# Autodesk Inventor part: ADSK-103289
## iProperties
Shininess: 0.0
Created: 2000-04
Part Number: ADSK-103289
Document SubType Name: Modeling
Stock Number: ADSK-103289
Density: 1 g/cm^3
Density: 0.0
Volumn: 0.0
Area: 0.0
PropertySet Name: Model Information
Control State: 0
Checked Out: False
Master: False
Author: gao
